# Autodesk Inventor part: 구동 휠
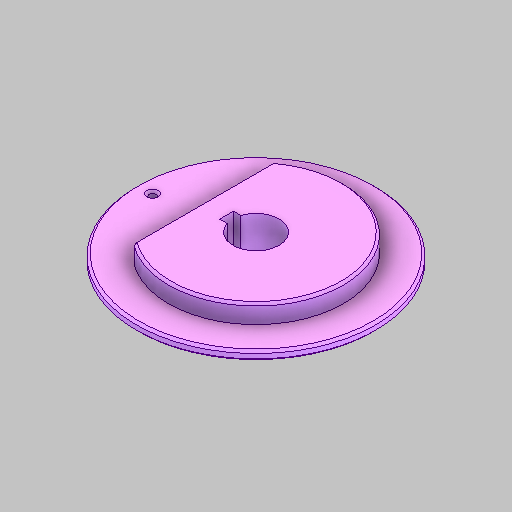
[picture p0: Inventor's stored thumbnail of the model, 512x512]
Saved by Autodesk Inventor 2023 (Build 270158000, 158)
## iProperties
Created: 2025-09
Part Number: 구동 휠
Material: 강철, 연강
Document SubType Name: Modeling
Designer: home
Density: 7.85 g/cm^3
Appearance: 기본값
Author: jhkim
Sending System: Autodesk Inventor 2026
Preprocessor: ST-DEVELOPER v20.1
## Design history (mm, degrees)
feature "솔리드1"
node "솔리드2"
